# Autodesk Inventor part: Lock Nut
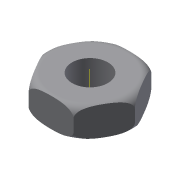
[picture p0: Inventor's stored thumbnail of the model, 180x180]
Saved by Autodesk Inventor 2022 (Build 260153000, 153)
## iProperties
Created: 2009-04
Part Number: Lock Nut
Document SubType Name: Modeling
Designer: Sham
Density: 1 g/cm^3
Material: Generic
Appearance: Default
Mass: 4.65064 g
Surface Area: 21.3319 cm^2
Volume: 4.65064 cm^3
Author: Sham
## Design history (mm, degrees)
sketch "Sketch1"
  geometry: L1 (7.5, 12.99)-(15, 0); L2 (15, 0)-(7.5, -12.99); L3 (7.5, -12.99)-(-7.5, -12.99); L4 (-7.5, -12.99)-(-15, 0); L5 (-15, 0)-(-7.5, 12.99); L6 (-7.5, 12.99)-(7.5, 12.99); C1 r 6 at (0, 0); 1 further point
  constraints: 12 end point, 1 centre point, 1 coincident, 13 other
  dimensions: "d0" = 30 distance of L1.end L4.end; "d1" = 12 diameter of C1
extrude "Extrusion1" new body sketch "Sketch1" distance "d2" = 10; taper "d3" = 0 deg
sketch "Sketch2"
  geometry: L1 (-12, 0)-(-12, -0.022); L2 (-15, 7)-(-15, 3); L3 (0, -2.87)-(0, 12.87) reference; A1 r 3 centre (-12, 7) between (-12, 10) and (-15, 7); A2 r 3 centre (-12, 3) between (-15, 3) and (-12, 0)
  constraints: 4 end point, 4 point on circle, 2 centre point, 1 tangent
revolve "Revolution1" sketch "Sketch2" stored, may be unused: angle "d7" = 90 deg
body "Solid1"
other parameters: "d6" = 90 deg
